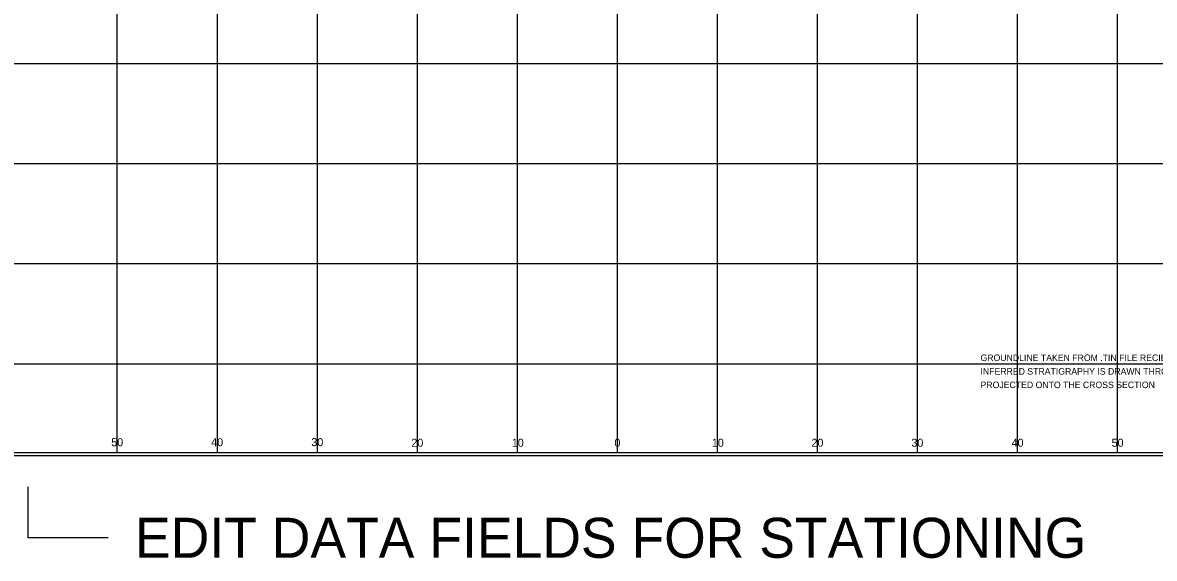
# Model space of a CAD drawing. Extents: x 278618 to 280654, y 171155 to 171855.
# Drawn here: x 280447.2 to 280560.4, y 171178.3 to 171231.9 of the extents above; entities that cross this region are included whole.
import ezdxf

# ---------------------------------------------------------------- set-up
doc = ezdxf.new("R2010")
doc.units = 0
for name, color, linetype in [('Exist Vertical Profile Ground Line', 7, 'Continuous'), ('Geotech Sheets and Borders Cell', 7, 'Continuous'), ('Prop Strc Sect_ Grid - minor', 7, 'Continuous'), ('Scratch_Level_4', 7, 'Continuous'), ('Sheet Plot Border Inside CELL', 7, 'Continuous')]:
    doc.layers.add(name, color=color, linetype=linetype)

msp = doc.modelspace()

# ---------------------------------------------------------------- linework, layer by layer
at = {"layer": 'Geotech Sheets and Borders Cell'}
msp.add_lwpolyline([(280436.69, 171293.86), (280586.69, 171293.86), (280586.69, 171188.86), (280436.69, 171188.86)], close=True, dxfattribs=at)
at = {"layer": 'Prop Strc Sect_ Grid - minor'}
for p, q in [((280456.69, 171188.86), (280456.69, 171293.86)), ((280466.69, 171188.86), (280466.69, 171293.86)), ((280476.69, 171188.86), (280476.69, 171293.86)), ((280486.69, 171188.86), (280486.69, 171293.86)), ((280496.69, 171188.86), (280496.69, 171293.86)), ((280506.69, 171188.86), (280506.69, 171293.86)), ((280516.69, 171188.86), (280516.69, 171293.86)), ((280526.69, 171188.86), (280526.69, 171293.86)), ((280536.69, 171188.86), (280536.69, 171285.96)), ((280546.69, 171188.86), (280546.69, 171285.96)), ((280556.69, 171188.86), (280556.69, 171285.96)), ((280586.69, 171227.74), (280436.69, 171227.74)), ((280586.69, 171217.74), (280436.69, 171217.74)), ((280586.69, 171207.74), (280436.69, 171207.74)), ((280586.69, 171197.74), (280436.69, 171197.74))]:
    msp.add_line(p, q, dxfattribs=at)
at = {"layer": 'Scratch_Level_4'}
msp.add_lwpolyline([(280455.78, 171180.37), (280447.76, 171180.37), (280447.76, 171185.45)], dxfattribs=at)
at = {"layer": 'Sheet Plot Border Inside CELL'}
msp.add_lwpolyline([(280421.17, 171188.58), (280587.94, 171188.58), (280587.94, 171294.14), (280421.17, 171294.14)], close=True, dxfattribs=at)

# ---------------------------------------------------------------- texts
at = {"layer": 'Exist Vertical Profile Ground Line'}
for s, p in [('GROUNDLINE TAKEN FROM .TIN FILE RECIEVED BY NCDOT DATED 03/28/2019.', (280542.99, 171198.04)), ('INFERRED STRATIGRAPHY IS DRAWN THROUGH THE BORINGS WITH BOTH ', (280542.99, 171196.68)), ('PROJECTED ONTO THE CROSS SECTION', (280542.99, 171195.33))]:
    msp.add_text(s, height=0.65, dxfattribs=at).set_placement(p)
at = {"layer": 'Geotech Sheets and Borders Cell'}
for s, p in [('50', (280456.08, 171189.52)), ('40', (280466.08, 171189.52)), ('30', (280476.09, 171189.53)), ('20', (280486.09, 171189.47)), ('10', (280496.13, 171189.47)), ('0', (280506.39, 171189.47)), ('10', (280516.13, 171189.47)), ('20', (280526.09, 171189.47)), ('30', (280536.08, 171189.47)), ('40', (280546.1, 171189.47)), ('50', (280556.1, 171189.47))]:
    msp.add_text(s, height=0.8, dxfattribs=at).set_placement(p)
at = {"layer": 'Scratch_Level_4'}
msp.add_text('EDIT DATA FIELDS FOR STATIONING', height=4, dxfattribs=at).set_placement((280458.46, 171178.37))

doc.saveas('drawing.dxf')
